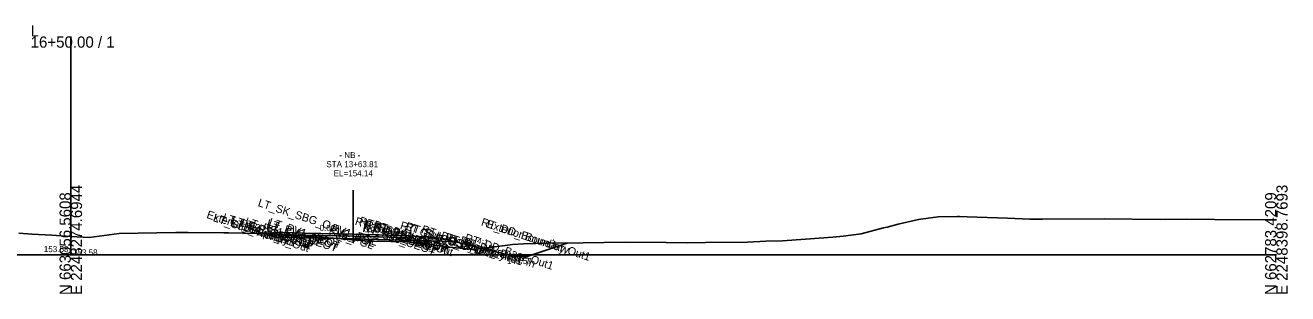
# Model space of a CAD drawing. Extents: x -26 to 2603, y -10 to 9566.
# Drawn here: x 288.7 to 602.8, y 6490.3 to 6557.2 of the extents above; entities that cross this region are included whole.
import ezdxf

# ---------------------------------------------------------------- set-up
doc = ezdxf.new("R2010")
doc.units = 0
for name, color, linetype in [('Exist Cross Section Cell', 7, 'Continuous'), ('Exist XS Center Line Elevation Label', 7, 'Continuous'), ('Exist XS Ground Line', 7, 'Continuous'), ('Prop CMT Ditch DDE', 7, 'Continuous'), ('Prop CMT Pvmt Course 1', 7, 'Continuous'), ('Prop CMT Pvmt Course 2', 7, 'Continuous'), ('Prop CMT Pvmt Surface', 7, 'Continuous'), ('Prop CMT Pvmt Surface Overlay', 7, 'Continuous'), ('Prop CMT Pvmt Surface Shoulder', 7, 'Continuous'), ('Prop CMT Shld Paved Course 1', 7, 'Continuous'), ('Prop CMT Shld Paved Course 2', 7, 'Continuous'), ('Prop CMT Slope Grass', 7, 'Continuous'), ('Prop CMT Subgrade Earthwork', 7, 'Continuous'), ('Prop XS Ditch Standard Text', 7, 'Continuous'), ('Prop XS SE Text', 7, 'Continuous'), ('Prop XS Side Slope Text', 7, 'Continuous'), ('Prop XS Vertical Lines Alignments', 7, 'Continuous'), ('Scratch_Level_1', 7, 'Continuous'), ('Scratch_Level_9', 7, 'Continuous')]:
    doc.layers.add(name, color=color, linetype=linetype)

msp = doc.modelspace()

# ---------------------------------------------------------------- linework, layer by layer
at = {"layer": 'Exist Cross Section Cell'}
for p, q in [((300, 6500), (300, 6554.44)), ((0, 6500), (300, 6500)), ((300, 6500), (600, 6500))]:
    msp.add_line(p, q, dxfattribs=at)
at = {"layer": 'Exist XS Ground Line'}
for p, q in [((496.69, 6505.28), (502.27, 6506.71)), ((502.27, 6506.71), (503.16, 6506.94)), ((503.16, 6506.94), (505.86, 6507.63)), ((505.86, 6507.63), (510.92, 6508.86)), ((510.92, 6508.86), (513.36, 6509.17)), ((513.36, 6509.17), (515.83, 6509.49)), ((515.83, 6509.49), (520.62, 6509.59)), ((520.62, 6509.59), (521.16, 6509.59)), ((521.16, 6509.59), (523.04, 6509.51)), ((523.04, 6509.51), (533.1, 6509.12)), ((533.1, 6509.12), (538.63, 6508.94)), ((538.63, 6508.94), (539.04, 6508.93)), ((539.04, 6508.93), (541.85, 6508.88)), ((541.85, 6508.88), (557.12, 6508.96)), ((557.12, 6508.96), (571.16, 6508.82)), ((571.16, 6508.82), (577.56, 6508.92)), ((577.56, 6508.92), (584.58, 6508.86)), ((584.58, 6508.86), (597.75, 6508.76)), ((597.75, 6508.76), (600, 6508.76)), ((287.06, 6505.39), (290.27, 6505.19)), ((290.27, 6505.19), (295.3, 6504.88)), ((295.3, 6504.88), (300, 6504.58)), ((300, 6504.58), (304.54, 6504.3)), ((304.54, 6504.3), (312.06, 6505.35)), ((312.06, 6505.35), (326.17, 6505.6)), ((326.17, 6505.6), (329.2, 6505.57)), ((329.2, 6505.57), (338.07, 6505.51)), ((338.07, 6505.51), (338.61, 6505.5)), ((338.61, 6505.5), (339.24, 6505.49)), ((339.24, 6505.49), (346.4, 6505.31)), ((346.4, 6505.31), (348.46, 6505.26)), ((348.46, 6505.26), (353.42, 6504.95)), ((353.42, 6504.95), (361.36, 6504.47)), ((361.36, 6504.47), (363.8, 6504.3)), ((363.8, 6504.3), (364.11, 6504.28)), ((364.11, 6504.28), (365.37, 6504.17)), ((365.37, 6504.17), (374.17, 6503.46)), ((374.17, 6503.46), (375.22, 6503.43)), ((375.22, 6503.43), (384.11, 6503.28)), ((472.94, 6503.39), (477.08, 6503.53)), ((477.08, 6503.53), (482.87, 6503.92)), ((482.87, 6503.92), (489.6, 6504.39)), ((489.6, 6504.39), (492.2, 6504.66)), ((492.2, 6504.66), (496.69, 6505.28)), ((384.11, 6503.28), (388.96, 6502.67)), ((388.96, 6502.67), (393.41, 6502)), ((393.41, 6502), (400.11, 6501.36)), ((400.11, 6501.36), (408.08, 6502.37)), ((408.08, 6502.37), (409.9, 6502.62)), ((409.9, 6502.62), (412.68, 6502.74)), ((412.68, 6502.74), (418.8, 6502.9)), ((418.8, 6502.9), (427.49, 6503.03)), ((427.49, 6503.03), (432.68, 6503.09)), ((432.68, 6503.09), (438.25, 6503.15)), ((438.25, 6503.15), (448.15, 6503.05)), ((448.15, 6503.05), (453.39, 6503)), ((453.39, 6503), (457.98, 6503.07)), ((457.98, 6503.07), (468.41, 6503.18)), ((468.41, 6503.18), (472.94, 6503.39))]:
    msp.add_line(p, q, dxfattribs=at)
at = {"layer": 'Prop CMT Ditch DDE'}
msp.add_lwpolyline([(402.29, 6501.63), (402.3, 6501.63), (410.56, 6499.57), (413.56, 6499.57), (423.81, 6502.98)], dxfattribs=at)
at = {"layer": 'Prop CMT Pvmt Course 1'}
for points in [[(370.23, 6505.14), (358.23, 6505.44)], [(358.23, 6505.44), (358.23, 6504.94)], [(358.23, 6504.94), (370.23, 6504.64)], [(370.23, 6504.64), (370.23, 6505.14)], [(370.23, 6505.14), (382.24, 6504.84)], [(370.23, 6504.64), (370.23, 6505.14)], [(382.24, 6504.34), (370.23, 6504.64)], [(382.24, 6504.84), (382.24, 6504.34)]]:
    msp.add_lwpolyline(points, dxfattribs=at)
at = {"layer": 'Prop CMT Pvmt Course 2'}
for points in [[(370.23, 6504.64), (358.23, 6504.94)], [(358.23, 6504.94), (358.23, 6504.27)], [(358.23, 6504.27), (370.23, 6503.97)], [(370.23, 6503.97), (370.23, 6504.64)], [(370.23, 6503.97), (370.23, 6504.64)], [(370.23, 6504.64), (382.24, 6504.34)], [(382.24, 6503.67), (370.23, 6503.97)], [(382.24, 6504.34), (382.24, 6503.67)]]:
    msp.add_lwpolyline(points, dxfattribs=at)
at = {"layer": 'Prop CMT Pvmt Surface'}
for points in [[(370.23, 6505.14), (358.23, 6505.44)], [(370.23, 6505.14), (382.24, 6504.84)]]:
    msp.add_lwpolyline(points, dxfattribs=at)
at = {"layer": 'Prop CMT Pvmt Surface Overlay'}
for points in [[(370.23, 6505.14), (358.23, 6505.44)], [(370.23, 6505.14), (382.24, 6504.84)]]:
    msp.add_lwpolyline(points, dxfattribs=at)
at = {"layer": 'Prop CMT Pvmt Surface Shoulder'}
for points in [[(358.23, 6505.44), (352.23, 6505.59)], [(382.24, 6504.84), (384.24, 6504.79)]]:
    msp.add_lwpolyline(points, dxfattribs=at)
at = {"layer": 'Prop CMT Shld Paved Course 1'}
for points in [[(358.23, 6505.44), (352.23, 6505.59), (351.74, 6505.1)], [(351.74, 6505.1), (358.23, 6504.94)], [(358.23, 6504.94), (358.23, 6505.44)], [(382.24, 6504.84), (384.24, 6504.79), (384.75, 6504.27)], [(382.24, 6504.34), (382.24, 6504.84)], [(384.75, 6504.27), (382.24, 6504.34)]]:
    msp.add_lwpolyline(points, dxfattribs=at)
at = {"layer": 'Prop CMT Shld Paved Course 2'}
for points in [[(358.23, 6504.94), (351.74, 6505.1), (351.24, 6505.12), (350.59, 6504.47)], [(350.59, 6504.47), (358.23, 6504.27)], [(358.23, 6504.27), (358.23, 6504.94)], [(382.24, 6504.34), (384.75, 6504.27), (385.25, 6504.26), (385.94, 6503.58)], [(382.24, 6503.67), (382.24, 6504.34)], [(385.94, 6503.58), (382.24, 6503.67)]]:
    msp.add_lwpolyline(points, dxfattribs=at)
at = {"layer": 'Prop CMT Slope Grass'}
for points in [[(350.22, 6505.52), (349.02, 6505.22)], [(352.23, 6505.59), (350.22, 6505.52)], [(384.24, 6504.79), (392.24, 6504.15)], [(392.24, 6504.15), (402.29, 6501.63)]]:
    msp.add_lwpolyline(points, dxfattribs=at)
at = {"layer": 'Prop CMT Subgrade Earthwork'}
msp.add_line((350.59, 6504.47), (349.02, 6505.22), dxfattribs=at)
for points in [[(358.23, 6504.27), (350.59, 6504.47)], [(350.59, 6504.47), (395.47, 6503.34)], [(370.23, 6503.97), (358.23, 6504.27)], [(370.23, 6503.97), (382.24, 6503.67)], [(382.24, 6503.67), (385.94, 6503.58)], [(385.94, 6503.58), (395.47, 6503.34)]]:
    msp.add_lwpolyline(points, dxfattribs=at)
at = {"layer": 'Prop XS Vertical Lines Alignments'}
msp.add_line((370.23, 6516.14), (370.23, 6503.14), dxfattribs=at)

# ---------------------------------------------------------------- texts
at = {"layer": 'Exist Cross Section Cell'}
for s, p in [('L', (290, 6554.44)), ('16+50.00 / 1', (290, 6551.64))]:
    msp.add_text(s, height=2.8, dxfattribs=at).set_placement(p)
for s, p in [('E 2248274.6944', (302.8, 6490)), ('E 2248398.7693', (602.8, 6490)), ('N 663056.5608', (300, 6490)), ('N 662783.4209', (600, 6490))]:
    msp.add_text(s, height=2.8, rotation=90, dxfattribs=at).set_placement(p)
at = {"layer": 'Exist XS Center Line Elevation Label'}
for p in [(293.28, 6500.69), (300.53, 6499.87)]:
    msp.add_text('153.58', height=1.5, dxfattribs=at).set_placement(p)
at = {"layer": 'Prop XS Ditch Standard Text'}
msp.add_text('148.57', height=1.5, dxfattribs=at).set_placement((408.56, 6497.73))
at = {"layer": 'Prop XS SE Text'}
for p in [(361.9, 6506), (372.89, 6505.65)]:
    msp.add_text('0.025', height=1.5, rotation=358.5434, dxfattribs=at).set_placement(p)
at = {"layer": 'Prop XS Side Slope Text'}
for s, rotation, p in [('4:1', 345.9601, (400.98, 6502.93)), ('3:1', 18.4232, (418.45, 6501.72))]:
    msp.add_text(s, height=1.5, rotation=rotation, dxfattribs=at).set_placement(p)
at = {"layer": 'Prop XS Vertical Lines Alignments'}
for s, p in [('- NB -', (366.84, 6524.11)), ('STA 13+63.81', (363.59, 6521.86))]:
    msp.add_text(s, height=1.5, dxfattribs=at).set_placement(p)
at = {"layer": 'Scratch_Level_1'}
msp.add_text('EL=154.14', height=1.5, dxfattribs=at).set_placement((365.42, 6519.61))
at = {"layer": 'Scratch_Level_9'}
for s, p in [('LT_SK_SBG_O', (346.41, 6512.21)), ('Exterior Boundary', (333.64, 6509.23)), ('LT_Sub_Trench_Out', (335.27, 6508.45)), ('LT_PS2_Shelf_Out', (337.61, 6508.55)), ('LT_GS_OS_CTL', (339.81, 6507.89)), ('LT_Slope_Fill', (339.7, 6507.24)), ('LT_PS2_OEOP', (342.15, 6507.21)), ('LT_PS1_OEOP', (343.18, 6507.52)), ('LT_Sub_OEOT', (348.49, 6506.43)), ('LT_PV2_OEOT', (348.58, 6507.06)), ('LT_PV1_OEOT', (349.12, 6507.39)), ('Sub_PGL', (364.04, 6504.96)), ('PV2_PGL', (364.13, 6505.59)), ('PV1_PGL', (364.67, 6505.92)), ('RT_Sub_Trench_Out', (370.57, 6507.58)), ('RT_PS2_Shelf_Out', (371.58, 6507.71)), ('RT_Sub_OEOT', (372.46, 6505.84)), ('RT_PV2_OEOT', (372.55, 6506.47)), ('RT_PV1_OEOT', (373.08, 6506.8)), ('RT_PS2_OEOP', (375.12, 6506.39)), ('RT_PS1_OEOP', (375.14, 6506.73)), ('RT_GS_OS_CTL', (381.79, 6506.53)), ('RT_Sub_OSS_DLT', (383.15, 6506.34)), ('LT_Sub_OSS_DLT', (383.19, 6506.33)), ('RT_DD_Boundary In1', (387.09, 6505.58)), ('RT_DD_Boundary Out1', (401.96, 6507.36)), ('Exterior Boundary', (403.33, 6506.91)), ('RT_Slope_Fill', (392.93, 6503.66)), ('RT_DD_Base In', (396.7, 6502.85)), ('RT_DD_Base Out1', (397.85, 6503.46))]:
    msp.add_text(s, height=2, rotation=341.787, dxfattribs=at).set_placement(p)

doc.saveas('drawing.dxf')
